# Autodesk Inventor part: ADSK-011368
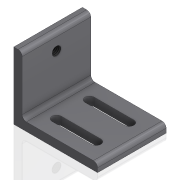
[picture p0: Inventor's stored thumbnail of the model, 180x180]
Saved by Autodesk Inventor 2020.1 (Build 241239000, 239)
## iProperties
Created: 1999-12
Part Number: ADSK-011368
Material: Acier doux
Document SubType Name: Modeling
Designer: sspink
Density: 7.86 g/cm^3
Appearance: Metal-Steel(Polish)
Mass: 252.75 g
Surface Area: 131.518 cm^2
Volume: 32.1565 cm^3
Control State: 0
Checked Out: False
Master: False
Shininess: 0.0
Length Units: 11269
Angle Units: 11279
Time Units: 11290
Mass Units: 11283
Length Display Precision: 3
Angle Display Precision: 2
Compacted: True
Cutlength: 2.06
Material Desc: ANGLE,HRS,.250X2.50X2.00
Material_Number: A084060
Dimensions: 63,5x50,8x52 mm
Mass: 0,253 kg
DocNumber: ADSK-011368.ipt
Folder: 01 - Themengebiete\Simplification\01 - Packaging machine\
VDS_Category: 3D Komponenten
Density: 0.0
Volumn: 0.0
Area: 0.0
PropertySet Name: Model Information
Author: sspink
Revision Number: -
Title: angle profile
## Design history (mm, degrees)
node "Rectangular Pattern2" dims "d26" = 20, "d28" = 25
node "Solide1"
  node "Extrusion1" dims "d4" = 52, "d5" = 0
  node "Fillet1" dims "d6" = 3.175
  node "Fillet2" dims "d7" = 3.175
  node "Extrusion2" dims "d12" = 50.8, "d13" = 0
  node "Hole1" dims "d17" = 6.647, "d18" = 9.525, "d19" = 6.35, "d20" = 60 deg, "d21" = 22.2, "d22" = 118 deg, "d30" = 16
workplane "Arbeitsebene1"
workplane "Arbeitsebene2"
sketch "Sketch2"
  geometry: L1 (9.475, 35)-(39.475, 35); L2 (39.475, 35)-(39.475, 42); L3 (39.475, 42)-(9.475, 42); L4 (9.475, 42)-(9.475, 35); L5 (-9.525, 52)-(-9.525, 0) reference; L6 (53.975, 0)-(53.975, 52) reference; L7 (53.975, 26)-(-9.525, 26); L8 (39.475, 38.5)-(9.475, 38.5); A1 r 3.5 centre (9.475, 38.5) between (9.475, 42) and (9.475, 35); A2 r 3.5 centre (39.475, 38.5) between (39.475, 35) and (39.475, 42)
  constraints: 12 end point, 4 point on circle, 2 centre point, 2 midpoint, 2 parallel, 2 perpendicular, 2 tangent, 1 horizontal
  dimensions: "d8" = 7 distance of L1.end L2.end; "d9" = 30 distance of L1.start L1.end; "d25" = 19 horizontal distance of L8.end L5.start; "d31" = 12.5 distance between parallel lines of L7 L8
sketch "Sketch3"
  geometry: L1 (0, 50.8)-(52, 50.8) reference; 2 further points
  constraints: 1 midpoint, 1 vertical alignment
  dimensions: "d29" = 12.5 distance from line of L1 point (26, 38.3)
node "Corps solides"
node "Corps surfaciques"
sketch "Sketch1"
  geometry: L1 (0, 0)-(-57.15, 0) reference; L2 (-57.15, 0)-(-57.15, 6.35); L3 (-57.15, 6.35)-(0, 6.35); L4 (0, 6.35)-(0, 0) reference; L5 (-57.15, 0)-(-63.5, 0); L6 (-63.5, 0)-(-63.5, 50.8); L7 (-63.5, 50.8)-(-57.15, 50.8); L8 (-57.15, 50.8)-(-57.15, 0)
  constraints: 16 end point, 4 parallel, 3 horizontal, 2 perpendicular, 1 vertical
  dimensions: "d0" = 50.8 distance of L5.end L6.end; "d1" = 6.35 distance of L6.end L7.end (= d2); "d2" = 6.35 distance of L3.end L1.start; "d3" = 57.15 distance of L1.start L1.end
